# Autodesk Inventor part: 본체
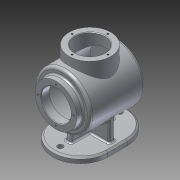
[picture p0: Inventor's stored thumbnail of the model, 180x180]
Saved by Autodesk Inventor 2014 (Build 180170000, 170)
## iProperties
Created: 2016-04
Part Number: 본체
Material: Aluminum 6061
Document SubType Name: Modeling
Designer: user
Density: 2.71 g/cm^3
Appearance: Aluminum - Flat
Mass: 961.482 g
Surface Area: 1326.62 cm^2
Volume: 354.79 cm^3
Author: user
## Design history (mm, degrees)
sketch "Sketch1"
  geometry: L1 (45.841, 110.899)-(-45.841, -110.899); A1 r 120 centre (0, 0) between (45.841, 110.899) and (-45.841, -110.899); 1 further point
  constraints: 2 end point, 2 point on circle, 1 centre point, 1 coincident, 1 midpoint
  dimensions: "d0" = 240 diameter of A1
revolve "Revolution1" sketch "Sketch1" stored, may be unused: angle "d1" = 90 deg
sketch "Sketch2"
  geometry: L1 (109.378, 41.54)-(-109.378, -41.54); A1 r 117 centre (0, 0) between (109.378, 41.54) and (-109.378, -41.54); 1 further point
  constraints: 2 end point, 2 point on circle, 1 centre point, 1 coincident, 1 midpoint
  dimensions: "d2" = 234 diameter of A1
revolve "Revolution2" sketch "Sketch2" stored, may be unused: angle "d3" = 90 deg
workplane "Work Plane1"
sketch "Sketch3"
  geometry: L1 (-186.134, 164.451)-(186.134, 164.451); L2 (186.134, 164.451)-(186.134, -164.451); L3 (186.134, -164.451)-(-186.134, -164.451); L4 (-186.134, -164.451)-(-186.134, 164.451); 3 further points
  constraints: 8 end point, 2 midpoint, 2 parallel, 1 horizontal, 1 horizontal alignment, 1 perpendicular, 1 vertical alignment
  dimensions: "d5" = 372.26754 distance of L1.start L1.end; "d6" = 328.90283 distance of L3.end L1.start
extrude "Extrusion1" cut sketch "Sketch3" distance "d7" = 11111; taper "d8" = 0 deg
sketch "Sketch5"
  geometry: C1 r 39.862 at (0, 0) reference; C2 r 50 at (0, 0); C3 r 47 at (0, 0)
  constraints: 3 coincident, 2 centre point
  dimensions: "d9" = 100 diameter of C2; "d88" = 94 diameter of C3
extrude "Extrusion2" join sketch "Sketch5" distance "d10" = 100; taper "d11" = 0 deg
sketch "Sketch6"
  geometry: C1 r 50 at (0, 0) reference; C2 r 38 at (0, 0)
  constraints: 1 centre point, 1 coincident
  dimensions: "d12" = 76 diameter of C2
extrude "Extrusion3" join sketch "Sketch6" distance "d13" = 12; taper "d14" = 0 deg
workplane "Work Plane2"
sketch "Sketch7"
  geometry: C1 r 50 at (0, 0) reference; C2 r 47 at (0, 0); 1 further point
  constraints: 1 centre point
  dimensions: "d15" = 3 radial gap between concentric circles of C1 C2
extrude "Extrusion4" cut sketch "Sketch7" stored distance "d16" = 94; taper "d17" = 0 deg
workplane "Work Plane3"
sketch "Sketch8"
  geometry: L1 (-127.5, 0)-(7.5, 0); L2 (-77.5, 50)-(-42.5, 50); L3 (-77.5, -50)-(-42.5, -50); L4 (-110, 50)-(-10, 50) reference; A1 r 50 centre (-42.5, 0) between (-42.5, 50) and (-42.5, -50); A2 r 50 centre (-77.5, 0) between (-77.5, 50) and (-77.5, -50); 3 further points
  constraints: 6 end point, 4 point on circle, 3 horizontal alignment, 3 tangent, 2 centre point, 2 midpoint, 1 horizontal, 1 parallel, 1 vertical alignment
  dimensions: "d21" = 135 distance of L1.start L1.end; "d23" = 100 diameter of A1; "d24" = 100 diameter of A2; "d25" = 50 distance of L1.start A2.centre; "d26" = 50 distance of L1.end A1.centre
extrude "Extrusion5" join sketch "Sketch8" distance "d27" = 10; taper "d28" = 0 deg
sketch "Sketch9"
  geometry: L1 (-50, -69)-(50, -69) reference; L2 (50, -69)-(50, -79) reference; L3 (50, -79)-(-50, -79) reference; L4 (-50, -79)-(-50, -69) reference; L5 (-40, -69)-(-40, -24.678); L6 (40, -24.678)-(40, -69); C1 r 47 at (0, 0) reference; C2 r 50 at (0, 0) reference; A1 r 47 centre (0, 0) between (-40, -24.678) and (40, -24.678); 1 further point
  constraints: 4 end point, 2 point on circle, 2 point on line, 1 centre point, 1 coincident, 1 concentric, 1 parallel, 1 perpendicular
  dimensions: "d30" = 40 distance from line of point (0, 0) L5; "d31" = 40 horizontal distance of L6.start point (0, 0)
extrude "Extrusion6" join sketch "Sketch9" stored distance "d32" = 10; taper "d33" = 0 deg
sketch "Sketch10"
  geometry: L1 (127.5, -69)-(77.5, -69) reference; L2 (65, -69)-(65, -30) reference; L3 (110, -50)-(10, -50) reference; L4 (77.5, -69)-(42.5, -69) reference; L5 (100, -69)-(96.65, -50); L6 (100, -69)-(152.824, -69); 1 further point
  constraints: 4 end point, 2 point on line, 1 horizontal
  dimensions: "d34" = 100 deg angle of L6 L5; "d35" = 35 distance from line of L5.start L2
feature "Rib1" sketch "Sketch10" dims "d36" = 1, "d37" = 10, "d38" = 0, "d39" = 0, "d40" = 1, "d41" = 1
mirror "Mirror1"
fillet "Fillet1" dims "d42" = 3
fillet "Fillet2" dims "d43" = 3
chamfer "Chamfer1" distance "d44" = 3; stored, may be unused: second distance "d45" = 2, angle "d46" = 45 deg
sketch "Sketch11"
  geometry: C1 r 38 at (0, 0) reference; C2 r 27 at (0, 0)
  constraints: 1 centre point, 1 coincident
  dimensions: "d47" = 54 diameter of C2
extrude "Extrusion7" cut sketch "Sketch11" distance "d48" = 15; taper "d49" = 0 deg
workplane "Work Plane4"
sketch "Sketch12"
  geometry: L1 (110, -50)-(10, -50) reference; C1 r 38 at (60, 0); 2 further points
  constraints: 1 centre point, 1 horizontal alignment, 1 midpoint, 1 vertical alignment
  dimensions: "d51" = 76 diameter of C1
extrude "Extrusion8" join sketch "Sketch12" stored distance "d52" = 15; taper "d53" = 0 deg
sketch "Sketch13"
  geometry: C1 r 38 at (0, 0) reference; C2 r 27 at (0, 0); 1 further point
  constraints: 1 centre point, 1 coincident
  dimensions: "d54" = 54 diameter of C2
extrude "Extrusion9" cut sketch "Sketch13" stored distance "d55" = 15; taper "d56" = 0 deg
fillet "Fillet4" dims "d58" = 5
fillet "Fillet5" dims "d59" = 3
chamfer "Chamfer2" distance "d60" = 1; stored, may be unused: second distance "d61" = 2, angle "d62" = 45 deg
chamfer "Chamfer3" distance "d63" = 1; stored, may be unused: second distance "d64" = 2, angle "d65" = 45 deg
sketch "Sketch14" dims "d66" = 65
  geometry: C1 r 28 at (0, 0) reference; 3 further points
  constraints: 1 coincident, 1 vertical alignment, 2 other
hole "Hole1" sketch "Sketch14" at (0, 32.5) diameter "d67" = 3.242; stored, may be unused: countersink angle "d71" = 90 deg, drill point angle "d73" = 118 deg; dims "d68" = 8, "d69" = 4, "d70" = 2, "d72" = 10
pattern_circular "Circular Pattern1" dims angle "d75" = 360 deg
sketch "Sketch15" dims "d77" = 65
  geometry: C1 r 28 at (0, 0) reference; 2 further points
  constraints: 1 coincident, 1 vertical alignment, 2 other
hole "Hole2" sketch "Sketch15" at (0, 32.5) diameter "d78" = 3.242; stored, may be unused: countersink angle "d82" = 90 deg, drill point angle "d84" = 118 deg; dims "d79" = 8, "d80" = 4, "d81" = 2, "d83" = 10
pattern_circular "Circular Pattern2" dims angle "d86" = 360 deg
workplane "Work Plane5"
sketch "Sketch18"
  geometry: 2 further points
  constraints: 1 coincident, 1 other
emboss "Emboss1" sketch "Sketch18" dims "d0" = 240, "d91" = 0.5, "d92" = 0
sketch "Sketch19"
  geometry: L1 (52, 37)-(52, 8) reference; L2 (68, 8)-(68, 37) reference; C1 r 5 at (6, 0); C2 r 5 at (114, 0); A1 r 47 centre (77.5, 0) between (77.5, -47) and (77.5, 47) reference; A2 r 47 centre (42.5, 0) between (42.5, 47) and (42.5, -47) reference; 1 further point
  constraints: 2 centre point, 2 horizontal alignment
  dimensions: "d93" = 10 diameter of C1; "d94" = 46 distance from line of L1 C1.centre; "d95" = 10 diameter of C2; "d96" = 46 distance from line of L2 C2.centre
extrude "Extrusion10" cut sketch "Sketch19" distance "d97" = 94; taper "d98" = 0 deg
body "Solid1"
node "Project Cut Edges1"
node "Project Cut Edges2"
other parameters: "d18" = -79, "d50" = -144
